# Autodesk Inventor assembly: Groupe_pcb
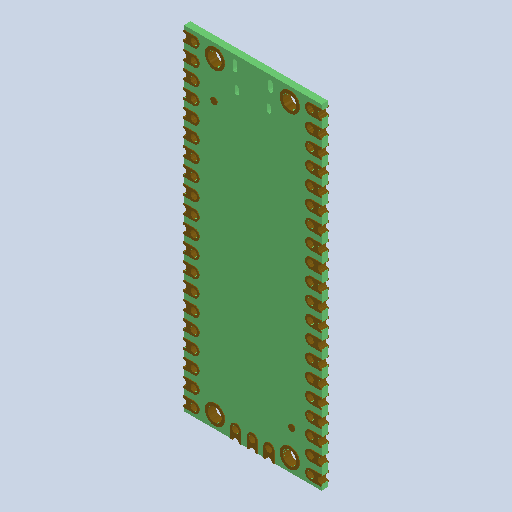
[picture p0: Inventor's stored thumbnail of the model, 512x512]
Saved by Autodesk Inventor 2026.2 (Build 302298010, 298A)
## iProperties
Created: 2026-10
Part Number: Groupe_pcb
Document SubType Name: Assembly
Designer: mel
Author: mel
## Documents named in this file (7)
- D:\travail\année 2026-2027\1 sti2d IT\poubelle à verre\raspberry-pico-2-microcontroller-rp2350-1.snapshot.5\raspberry_pico_2\raspberry_pico_2\Groupe_pcb.iam
- D:\travail\année 2026-2027\1 sti2d IT\poubelle à verre\raspberry-pico-2-microcontroller-rp2350-1.snapshot.5\raspberry_pico_2\raspberry_pico_2\PCB.ipt
- D:\travail\année 2026-2027\1 sti2d IT\poubelle à verre\raspberry-pico-2-microcontroller-rp2350-1.snapshot.5\raspberry_pico_2\raspberry_pico_2\lateral_castel_holes.iam
- D:\travail\année 2026-2027\1 sti2d IT\poubelle à verre\raspberry-pico-2-microcontroller-rp2350-1.snapshot.5\raspberry_pico_2\raspberry_pico_2\castel_holes_debug.iam
- D:\travail\année 2026-2027\1 sti2d IT\poubelle à verre\raspberry-pico-2-microcontroller-rp2350-1.snapshot.5\raspberry_pico_2\raspberry_pico_2\mounting_pads.iam
- D:\travail\année 2026-2027\1 sti2d IT\poubelle à verre\raspberry-pico-2-microcontroller-rp2350-1.snapshot.5\raspberry_pico_2\raspberry_pico_2\TP_noname001.ipt
- D:\travail\année 2026-2027\1 sti2d IT\poubelle à verre\raspberry-pico-2-microcontroller-rp2350-1.snapshot.5\raspberry_pico_2\raspberry_pico_2\test_point_round001.ipt
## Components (6 placed, 6 different names)
1. 2597
2. 2620 [sub-assembly]
3. 2624 [sub-assembly]
4. 2629 [sub-assembly]
5. 2630
6. 2631
